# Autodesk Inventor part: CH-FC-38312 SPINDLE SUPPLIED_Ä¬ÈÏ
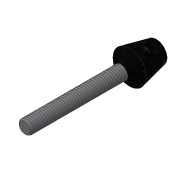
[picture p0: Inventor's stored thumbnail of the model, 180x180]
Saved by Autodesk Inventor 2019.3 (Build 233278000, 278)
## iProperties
Created: 2012-09
Part Number: CH-FC-38312 SPINDLE SUPPLIED_Ä¬ÈÏ
Material: Ogólny
Document SubType Name: Modeling
Designer: CADENGINEERING4
Density: 1 g/cm^3
Appearance: Domyślna
Author: CADENGINEERING4
Revision Number: ÈÎºÎ
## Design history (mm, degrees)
feature "NONE"
node "Bryła1"
